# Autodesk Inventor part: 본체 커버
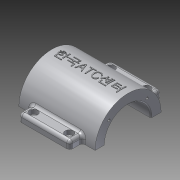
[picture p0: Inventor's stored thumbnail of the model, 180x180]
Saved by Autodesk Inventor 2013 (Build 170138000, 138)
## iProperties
Company: 한국ATC센터
Created: 2014-02
Part Number: 본체 커버
Document SubType Name: Modeling
Designer: KYOUNG IL JANG
Density: 2.71 g/cm^3
Mass: 199.244 g
Surface Area: 195.422 cm^2
Volume: 73.522 cm^3
Material: 알루미늄-6061
Vendor: CBT Solutions
Author: KYOUNG IL JANG
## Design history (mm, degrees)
sketch "스케치1"
  geometry: L1 (-45, 40)-(45, 40); L2 (45, 40)-(45, -40); L3 (45, -40)-(-45, -40); L4 (-45, -40)-(-45, 40); 3 further points
  constraints: 8 end point, 2 midpoint, 2 parallel, 1 horizontal, 1 horizontal alignment, 1 perpendicular, 1 vertical alignment
  dimensions: "d0" = 90 distance of L2.end L3.end; "d1" = 80 distance of L1.end L2.end
extrude "돌출1" new body sketch "스케치1" distance "d2" = 10; taper "d3" = 0 deg
sketch "스케치2"
  geometry: L1 (40, 0)-(-40, 0) reference; C1 r 32.5 at (0, 80); 2 further points
  constraints: 1 centre point, 1 midpoint, 1 vertical alignment
  dimensions: "d4" = 65 diameter of C1; "d5" = 80 distance from line of C1.centre L1
extrude "돌출2" join sketch "스케치2" stored distance "d6" = 75; taper "d7" = 0 deg
sketch "스케치3"
  geometry: L1 (-7.5, -20)-(7.5, -20); L2 (7.5, 20)-(-7.5, 20); A1 r 20 centre (7.5, 0) between (7.5, -20) and (7.5, 20); A2 r 20 centre (-7.5, 0) between (-7.5, 20) and (-7.5, -20); 2 further points
  constraints: 4 end point, 4 point on circle, 4 tangent, 2 centre point, 1 horizontal, 1 horizontal alignment, 1 midpoint, 1 parallel, 1 vertical alignment
  dimensions: "d8" = 20 radius of A2; "d9" = 55 dimension on A1 A2
extrude "돌출3" join sketch "스케치3" stored distance "d10" = 75; taper "d11" = 0 deg
fillet "모깎기1" dims "d12" = 10
sketch "스케치4"
  geometry: L1 (-45, 0)-(-45, 10) reference; L2 (37.5, 47.5)-(-37.5, 47.5) reference; L3 (-45, 10)-(-27.513, 47.5); 1 further point
  constraints: 2 end point, 1 point on line
  dimensions: "d13" = 25 deg angle of L3 L1
sketch "스케치5"
  geometry: L1 (-40, 0)-(-40, 10) reference; L2 (-40, 10)-(-22.912, 56.95); 2 further points
  constraints: 2 end point, 2 other
  dimensions: "d14" = 20 deg angle of L2 L1
feature "리브1" dims "d15" = 1, "d16" = 6, "d17" = 0
feature "리브2" dims "d18" = 1, "d19" = 6, "d20" = 0
fillet "모깎기2" dims "d21" = 3
fillet "모깎기3" dims "d22" = 3
fillet "모깎기4" dims "d23" = 3
fillet "모깎기5" dims "d24" = 3
fillet "모깎기6" dims "d25" = 3
fillet "모깎기7" dims "d26" = 3
fillet "모깎기8" dims "d27" = 3
sketch "스케치6"
  geometry: A1 r 10 centre (35, -30) between (35, -40) and (45, -30) reference; 1 further point
hole "구멍1" sketch "스케치6" at (35, -30) diameter "d28" = 10; stored, may be unused: countersink angle "d32" = 90 deg, drill point angle "d34" = 118 deg; dims "d29" = 6, "d30" = 4, "d31" = 2, "d33" = 8
hole "구멍2" diameter "d37" = 45; stored, may be unused: countersink angle "d41" = 90 deg, drill point angle "d43" = 118 deg; dims "d35" = 10, "d36" = 10, "d38" = 6, "d39" = 4, "d40" = 2, "d42" = 8
sketch "스케치7"
  geometry: C1 r 22.5 at (0, 0) reference; 2 further points
  dimensions: "d44" = 135 deg dimension on C1.centre point (-18.738, 18.738) point (80, 0); "d45" = 26.5 distance of point (-18.738, 18.738) C1.centre
hole "구멍3" sketch "스케치7" at (-18.738, 18.738) diameter "d46" = 2.459; stored, may be unused: countersink angle "d50" = 90 deg, drill point angle "d52" = 118 deg; dims "d47" = 8, "d48" = 4, "d49" = 2, "d51" = 10
node "작업 평면1"
chamfer "모따기1" distance "d69" = 1; stored, may be unused: second distance "d70" = 2, angle "d71" = 45 deg
sketch "스케치9"
  geometry: L1 (-31.623, 87.5)-(-45, 87.5); L2 (-45, 87.5)-(-45, 72.5); L3 (-45, 72.5)-(-31.623, 72.5); A1 r 32.5 centre (0, 80) between (-31.623, 87.5) and (-31.623, 72.5) reference; 1 further point
  constraints: 6 end point, 2 parallel, 2 point on circle, 1 horizontal, 1 perpendicular
  dimensions: "d73" = 15 distance of L1.end L2.end; "d74" = 45 distance from line of A1.centre L2
extrude "돌출5" join sketch "스케치9" stored distance "d75" = 50; taper "d76" = 0 deg
fillet "모깎기10" dims "d77" = 3
fillet "모깎기11" dims "d78" = 3
sketch "스케치10"
  geometry: L1 (100.378, 66.389)-(0, 66.389); L2 (0, 66.389)-(0, -76.978); L3 (0, -76.978)-(100.378, -76.978); L4 (100.378, -76.978)-(100.378, 66.389); C1 r 32.5 at (0, 0) reference; 1 further point
  constraints: 8 end point, 2 parallel, 1 horizontal, 1 perpendicular, 1 point on line
extrude "돌출6" cut sketch "스케치10" stored distance "d79" = 10; taper "d80" = 0 deg
sketch "스케치11"
  geometry: C1 r 1.621 at (4.5, 4) reference; C2 r 1.621 at (39.5, 4) reference; 1 further point
hole "구멍5" sketch "스케치11" at (39.5, 4), (4.5, 4) diameter "d81" = 4.5; stored, may be unused: countersink angle "d85" = 90 deg, drill point angle "d87" = 118 deg; dims "d82" = 6, "d83" = 8, "d84" = 4.4, "d86" = 8
node "작업 평면2"
sketch "스케치12"
  geometry: 2 further points
  constraints: 1 coincident, 1 other
feature "엠보싱1" sketch "스케치12" dims "d8" = 20, "d9" = 55, "d88" = 0.5, "d89" = 0
node "솔리드1"
mirror "대칭1"
mirror "대칭2"
mirror "대칭3"
mirror "대칭4"
pattern_circular "원형 패턴1" dims angle "d54" = 360 deg
mirror "대칭5"
mirror "대칭6"
mirror "대칭7"
node "참조1"
node "참조2"
other parameters: "d56" = -117
